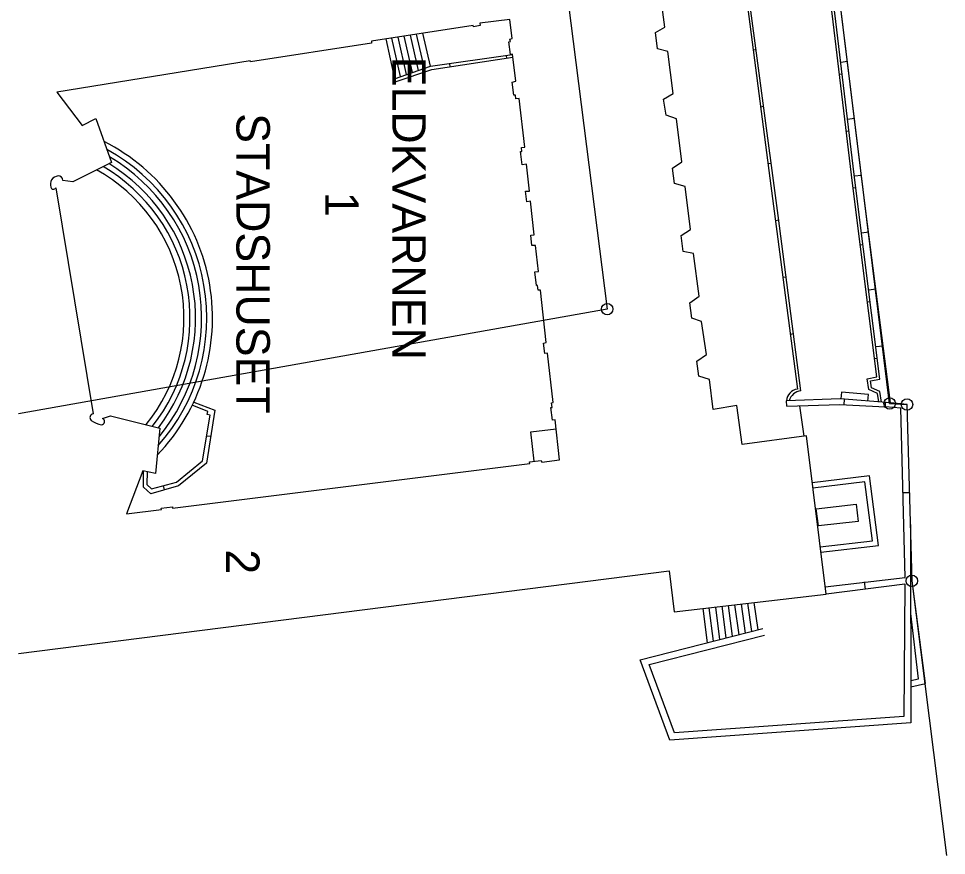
# Model space of a CAD drawing. Extents: x 1596643 to 1597288, y 13057194 to 13057957.
# Drawn here: x 1596648.4 to 1596745.5, y 13057297.9 to 13057385.4 of the extents above; entities that cross this region are included whole.
import ezdxf

# ---------------------------------------------------------------- set-up
doc = ezdxf.new("R2010")
doc.units = 0
for name, color, linetype in [('BAS byggnad anläggning L', 7, 'Continuous'), ('BAS byggnad anläggning T', 7, 'Continuous'), ('BAS fastighetsgräns samfällighet L', 7, 'Continuous'), ('BAS grind bom låst L', 7, 'Continuous'), ('BAS gränspunkt P', 7, 'Continuous'), ('BAS kajkant L', 7, 'Continuous'), ('BAS Level 18', 7, 'Continuous'), ('BAS Level 19', 7, 'Continuous'), ('BAS Level 36', 7, 'Continuous'), ('BAS Level 37', 7, 'Continuous'), ('BAS traktnamn T', 7, 'Continuous'), ('BAS trappa L', 7, 'Continuous')]:
    doc.layers.add(name, color=color, linetype=linetype)

msp = doc.modelspace()

# ---------------------------------------------------------------- linework, layer by layer
at = {"layer": 'BAS byggnad anläggning L'}
for points in [[(1596648.373, 13057318.998), (1596716.493, 13057327.632), (1596717.011, 13057323.345), (1596732.912, 13057325.204), (1596730.851, 13057341.773), (1596724.126, 13057340.882), (1596723.568, 13057344.966), (1596721.079, 13057344.543), (1596720.726, 13057347.682), (1596719.607, 13057348.015), (1596719.39, 13057349.6), (1596720.395, 13057350.293), (1596719.879, 13057353.737), (1596718.862, 13057354.08), (1596718.665, 13057355.695), (1596719.629, 13057356.409), (1596719.049, 13057360.848), (1596717.951, 13057361.079), (1596717.744, 13057362.756), (1596718.708, 13057363.357), (1596718.159, 13057367.858), (1596717.031, 13057368.19), (1596716.844, 13057369.796), (1596717.818, 13057370.438), (1596717.239, 13057374.959), (1596716.171, 13057375.322), (1596715.892, 13057377.008), (1596716.907, 13057377.621), (1596716.348, 13057382.019), (1596715.26, 13057382.291), (1596715.074, 13057383.988), (1596716.028, 13057384.549), (1596715.448, 13057389.029)], [(1596657.158, 13057343.581), (1596657.99, 13057343.858), (1596663.176, 13057342.59), (1596662.699, 13057337.843), (1596661.378, 13057338.125), (1596659.681, 13057333.608), (1596663.328, 13057334.054), (1596663.318, 13057334.197), (1596664.486, 13057334.342), (1596664.507, 13057334.2), (1596701.884, 13057338.866), (1596701.874, 13057339.059), (1596703.093, 13057339.194), (1596703.144, 13057339.021), (1596705.024, 13057339.27), (1596704.536, 13057343.455), (1596704.272, 13057343.424), (1596704.107, 13057344.725), (1596704.239, 13057344.743), (1596704.158, 13057345.228), (1596704.359, 13057345.264), (1596703.744, 13057350.442), (1596703.464, 13057350.404), (1596703.349, 13057351.491), (1596703.624, 13057351.532), (1596703.001, 13057357.038), (1596702.778, 13057357.007), (1596702.719, 13057357.523), (1596702.614, 13057357.505), (1596702.428, 13057358.937), (1596702.815, 13057358.989), (1596702.49, 13057361.713), (1596702.106, 13057361.69), (1596701.989, 13057362.78), (1596702.358, 13057362.799), (1596701.984, 13057366.324), (1596701.578, 13057366.272), (1596701.455, 13057367.368), (1596701.88, 13057367.401), (1596701.548, 13057370.194), (1596701.101, 13057370.142), (1596700.915, 13057371.524), (1596701.069, 13057371.539), (1596701.018, 13057371.959), (1596701.363, 13057371.985), (1596700.78, 13057377.082), (1596700.445, 13057377.051), (1596700.415, 13057377.446), (1596700.221, 13057377.427), (1596700.055, 13057378.808), (1596700.421, 13057378.88), (1596700.079, 13057381.715), (1596699.872, 13057381.692), (1596699.7, 13057383.014), (1596699.862, 13057383.035), (1596699.821, 13057383.309), (1596700.041, 13057383.348), (1596699.806, 13057385.342), (1596696.679, 13057384.956), (1596696.708, 13057384.724), (1596695.997, 13057384.591), (1596695.97, 13057384.736), (1596685.33, 13057383.08), (1596685.33, 13057382.867), (1596672.651, 13057380.935), (1596672.631, 13057381.026), (1596652.374, 13057377.734), (1596655.035, 13057374.255), (1596656.476, 13057375.001), (1596658.092, 13057370.401), (1596654.062, 13057368.349), (1596653.025, 13057368.509)], [(1596652.265, 13057367.745), (1596656.191, 13057344.077)], [(1596731.869, 13057334.138), (1596736.059, 13057334.61), (1596736.261, 13057332.82), (1596732.111, 13057332.348), (1596731.869, 13057334.138)]]:
    msp.add_lwpolyline(points, dxfattribs=at)
for centre, radius, start, end in [((1596652.568, 13057368.107), 0.869, 94.08562, 200.47887), ((1596652.522, 13057368.47), 0.505, 4.43355, 91.81471), ((1596652.018, 13057367.846), 0.267, 189.25103, 337.76001), ((1596656.231, 13057343.694), 0.385, 95.96228, 231.01452), ((1596657.366, 13057345.148), 2.229, 231.84999, 262.05534), ((1596657.054, 13057343.269), 0.328, 270.69869, 71.56505)]:
    msp.add_arc(centre, radius, start, end, dxfattribs=at)
at = {"layer": 'BAS fastighetsgräns samfällighet L'}
for points in [[(1596704.283, 13057400.099), (1596710, 13057355.034)], [(1596710, 13057355.034), (1596648.373, 13057344.063)]]:
    msp.add_lwpolyline(points, dxfattribs=at)
at = {"layer": 'BAS grind bom låst L'}
for points in [[(1596722.101, 13057406.691), (1596724.036, 13057391.871), (1596727.025, 13057368.742), (1596729.919, 13057346.671)], [(1596730.283, 13057346.486), (1596727.903, 13057364.824), (1596724.494, 13057390.486), (1596722.347, 13057407.045)], [(1596738.73, 13057345.297), (1596738.555, 13057346.414), (1596737.663, 13057346.816), (1596737.556, 13057347.518), (1596738.543, 13057347.705), (1596735.975, 13057368.27), (1596733.825, 13057386.017), (1596731.641, 13057403.216), (1596722.969, 13057402.244)], [(1596738.434, 13057345.321), (1596738.294, 13057346.215), (1596737.401, 13057346.617), (1596737.228, 13057347.75), (1596738.222, 13057347.938), (1596735.688, 13057368.235), (1596733.538, 13057385.982), (1596731.39, 13057402.897), (1596723.002, 13057401.957)], [(1596725.598, 13057382.18), (1596725.293, 13057382.139)], [(1596687.809, 13057378.828), (1596691.647, 13057380.119), (1596700.115, 13057381.412)], [(1596691.494, 13057380.453), (1596691.494, 13057380.453), (1596700.082, 13057381.684)], [(1596699.507, 13057381.319), (1596699.464, 13057381.596)], [(1596693.575, 13057380.413), (1596693.525, 13057380.745)], [(1596687.809, 13057378.828), (1596687.701, 13057379.148)], [(1596734.598, 13057379.637), (1596734.311, 13057379.602)], [(1596726.388, 13057376.232), (1596726.062, 13057376.189)], [(1596735.319, 13057373.68), (1596735.032, 13057373.645)], [(1596727.178, 13057370.284), (1596726.831, 13057370.238)], [(1596736.043, 13057367.724), (1596735.756, 13057367.688)], [(1596727.967, 13057364.336), (1596727.608, 13057364.29)], [(1596736.786, 13057361.77), (1596736.499, 13057361.734)], [(1596728.739, 13057358.386), (1596728.388, 13057358.341)], [(1596737.53, 13057355.817), (1596737.243, 13057355.781)], [(1596729.511, 13057352.436), (1596729.168, 13057352.392)], [(1596738.273, 13057349.863), (1596737.987, 13057349.827)], [(1596666.718, 13057345.316), (1596668.914, 13057344.474), (1596668.043, 13057338.903), (1596665.121, 13057336.559), (1596662.216, 13057335.718), (1596661.453, 13057336.418), (1596661.452, 13057338.109)], [(1596661.829, 13057338.028), (1596661.818, 13057336.683), (1596662.307, 13057336.237), (1596664.897, 13057336.924), (1596667.646, 13057339.146), (1596668.417, 13057343.955), (1596668.102, 13057344.025), (1596668.172, 13057344.32), (1596666.551, 13057344.968)], [(1596739.644, 13057345.219), (1596734.383, 13057345.647), (1596728.762, 13057345.439)], [(1596728.809, 13057344.869), (1596728.79, 13057345.44)], [(1596728.809, 13057344.869), (1596734.339, 13057345.058), (1596739.144, 13057344.805)], [(1596734.805, 13057345.034), (1596734.836, 13057345.611)], [(1596739.144, 13057344.805), (1596739.143, 13057345.263)], [(1596741.202, 13057326.936), (1596740.752, 13057344.688), (1596739.144, 13057344.805)], [(1596668.478, 13057341.689), (1596668.059, 13057341.754)], [(1596732.363, 13057329.614), (1596738.388, 13057330.307), (1596737.471, 13057337.6), (1596731.462, 13057336.865)], [(1596663.669, 13057336.139), (1596663.546, 13057336.564)], [(1596732.299, 13057330.173), (1596737.759, 13057330.801), (1596736.983, 13057336.973), (1596731.53, 13057336.306)], [(1596741.663, 13057335.819), (1596741.012, 13057335.8)], [(1596741.76, 13057332.499), (1596741.802, 13057311.748), (1596716.571, 13057309.929), (1596713.468, 13057318.337), (1596726.303, 13057321.596)], [(1596732.816, 13057325.978), (1596741.202, 13057326.936)], [(1596737.039, 13057325.724), (1596736.942, 13057326.498)], [(1596741.167, 13057326.245), (1596741.056, 13057312.404), (1596717.051, 13057310.673), (1596714.405, 13057317.845), (1596726.477, 13057320.91)], [(1596741.167, 13057326.245), (1596732.912, 13057325.204)]]:
    msp.add_lwpolyline(points, dxfattribs=at)
for centre, radius, start, end in [((1596730.151, 13057345.294), 1.396, 99.5635, 174.04038), ((1596730.433, 13057345.039), 1.455, 95.9183, 163.63268)]:
    msp.add_arc(centre, radius, start, end, dxfattribs=at)
at = {"layer": 'BAS gränspunkt P'}
for centre, radius in [((1596710.006, 13057355.041), 0.6), ((1596710.006, 13057355.041), 0.6), ((1596710.001, 13057355.034), 0.001), ((1596710.001, 13057355.034), 0.001), ((1596739.576, 13057345.158), 0.6), ((1596739.576, 13057345.158), 0.6), ((1596739.571, 13057345.151), 0.001), ((1596739.571, 13057345.151), 0.001), ((1596741.392, 13057345.053), 0.6), ((1596741.392, 13057345.053), 0.6), ((1596741.387, 13057345.046), 0.001), ((1596741.387, 13057345.046), 0.001), ((1596741.889, 13057326.601), 0.6), ((1596741.889, 13057326.601), 0.6), ((1596741.884, 13057326.594), 0.001), ((1596741.884, 13057326.594), 0.001)]:
    msp.add_circle(centre, radius, dxfattribs=at)
at = {"layer": 'BAS kajkant L'}
for points in [[(1596739.644, 13057345.219), (1596737.129, 13057365.019), (1596732.03, 13057406.376)], [(1596735.166, 13057380.94), (1596734.45, 13057380.851)], [(1596735.901, 13057374.985), (1596735.172, 13057374.895)], [(1596736.635, 13057369.03), (1596735.894, 13057368.939)], [(1596737.376, 13057363.076), (1596736.635, 13057362.982)], [(1596738.132, 13057357.124), (1596737.379, 13057357.028)], [(1596738.888, 13057351.172), (1596738.122, 13057351.074)], [(1596741.795, 13057315.501), (1596743.319, 13057315.85), (1596741.933, 13057326.588), (1596741.393, 13057345.051), (1596739.644, 13057345.219)], [(1596741.794, 13057316.169), (1596742.6, 13057316.336), (1596741.779, 13057323.184)]]:
    msp.add_lwpolyline(points, dxfattribs=at)
at = {"layer": 'BAS Level 18'}
msp.add_lwpolyline([(1596737.301, 13057345.412), (1596737.347, 13057346.093), (1596734.514, 13057346.337), (1596734.464, 13057345.641)], dxfattribs=at)
at = {"layer": 'BAS Level 19'}
for points in [[(1596730.639, 13057341.745), (1596730.182, 13057344.916)], [(1596702.365, 13057339.113), (1596702.019, 13057342.189), (1596704.648, 13057342.498)]]:
    msp.add_lwpolyline(points, dxfattribs=at)
at = {"layer": 'BAS Level 37'}
for points in [[(1596739.57, 13057345.151), (1596731.89, 13057407.514)], [(1596739.57, 13057345.151), (1596741.386, 13057345.046)], [(1596741.386, 13057345.046), (1596741.883, 13057326.594)], [(1596741.883, 13057326.594), (1596745.518, 13057297.856)]]:
    msp.add_lwpolyline(points, dxfattribs=at)
at = {"layer": 'BAS trappa L'}
for points in [[(1596690.865, 13057380.237), (1596690.049, 13057383.815)], [(1596691.494, 13057380.453), (1596690.694, 13057383.915)], [(1596686.822, 13057383.313), (1596687.717, 13057379.154)], [(1596688.346, 13057379.37), (1596687.467, 13057383.413)], [(1596688.976, 13057379.587), (1596688.113, 13057383.513)], [(1596689.605, 13057379.804), (1596688.758, 13057383.614)], [(1596690.235, 13057380.02), (1596689.403, 13057383.714)], [(1596687.717, 13057379.154), (1596691.494, 13057380.453)], [(1596720.021, 13057323.697), (1596720.466, 13057320.104)], [(1596721.133, 13057320.283), (1596720.692, 13057323.775)], [(1596721.8, 13057320.453), (1596721.364, 13057323.854)], [(1596722.468, 13057320.622), (1596722.036, 13057323.932)], [(1596723.136, 13057320.792), (1596722.708, 13057324.011)], [(1596723.803, 13057320.961), (1596723.38, 13057324.089)], [(1596724.471, 13057321.131), (1596724.052, 13057324.168)], [(1596725.139, 13057321.3), (1596724.724, 13057324.247)], [(1596725.806, 13057321.47), (1596725.396, 13057324.325)]]:
    msp.add_lwpolyline(points, dxfattribs=at)
for radius, start, end in [(20.689, 316.07317, 63.16991), (20.088, 318.30535, 61.35289), (18.915, 322.62423, 58.66636), (19.551, 320.53512, 59.5765), (17.7, 320.89075, 61.12681), (18.336, 321.82821, 59.78809)]:
    msp.add_arc((1596647.991, 13057354.11), radius, start, end, dxfattribs=at)

# ---------------------------------------------------------------- texts
at = {"layer": 'BAS byggnad anläggning T'}
msp.add_text('STADSHUSET', height=3.499, rotation=270, dxfattribs=at).set_placement((1596671.18, 13057375.55))
at = {"layer": 'BAS Level 36'}
for s, p in [('1', (1596680.477, 13057367.313)), ('2', (1596670.098, 13057329.899))]:
    msp.add_text(s, height=3.5, rotation=270, dxfattribs=at).set_placement(p)
at = {"layer": 'BAS traktnamn T'}
msp.add_text('ELDKVARNEN', height=3.5, rotation=270, dxfattribs=at).set_placement((1596687.51, 13057381.46))

doc.saveas('drawing.dxf')
